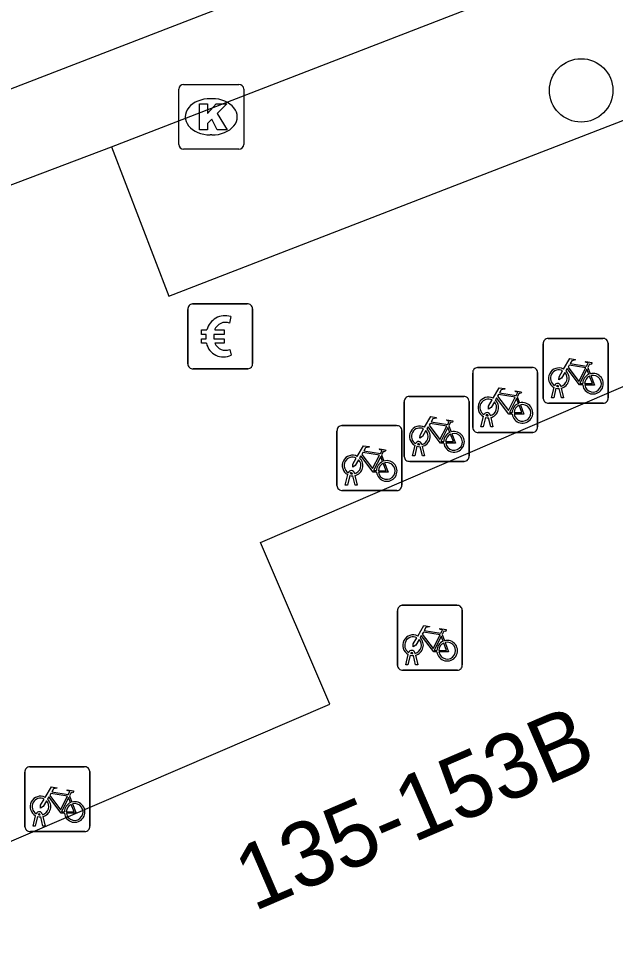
# Model space of a CAD drawing. Extents: x 159377 to 159983, y 382996 to 383595.
# Drawn here: x 159591.33 to 159600.52, y 383532.21 to 383546.59 of the extents above; entities that cross this region are included whole.
import ezdxf

# ---------------------------------------------------------------- set-up
doc = ezdxf.new("R2010")
doc.units = 0
for name, color, linetype in [('IMGEO_Betaalautomaat', 7, 'Continuous'), ('IMGEO_Boom', 7, 'Continuous'), ('IMGEO_Fietsenrek', 7, 'Continuous'), ('IMGEO_Kolk', 7, 'Continuous'), ('IMGEO_Pand', 7, 'Continuous'), ('IMGEO_Pand_nummerreeks', 7, 'Continuous'), ('IMGEO_Rijbaan_lokaal_gesloten', 7, 'Continuous'), ('IMGEO_Voetpad_open', 7, 'Continuous')]:
    doc.layers.add(name, color=color, linetype=linetype)

msp = doc.modelspace()

# ---------------------------------------------------------------- linework, layer by layer
at = {"layer": 'IMGEO_Betaalautomaat'}
for p, q in [((159593.934, 383541.268), (159593.934, 383542.109)), ((159593.934, 383542.109), (159593.934, 383541.268)), ((159594.009, 383542.192), (159594.85, 383542.192)), ((159594.85, 383542.192), (159594.009, 383542.192)), ((159594.933, 383542.118), (159594.933, 383541.277)), ((159594.933, 383541.277), (159594.933, 383542.118)), ((159594.596, 383541.997), (159594.579, 383541.897)), ((159594.217, 383541.656), (159594.217, 383541.724)), ((159594.338, 383541.724), (159594.338, 383541.656)), ((159594.583, 383541.491), (159594.605, 383541.404)), ((159594.859, 383541.193), (159594.018, 383541.193)), ((159594.018, 383541.193), (159594.859, 383541.193))]:
    msp.add_line(p, q, dxfattribs=at)
for points in [[(159594.217, 383541.724), (159594.148, 383541.724), (159594.148, 383541.793), (159594.227, 383541.793)], [(159594.349, 383541.793), (159594.496, 383541.793), (159594.496, 383541.724), (159594.338, 383541.724)], [(159594.222, 383541.587), (159594.148, 383541.587), (159594.148, 383541.656), (159594.217, 383541.656)], [(159594.338, 383541.656), (159594.496, 383541.656), (159594.496, 383541.587), (159594.352, 383541.587)]]:
    msp.add_lwpolyline(points, dxfattribs=at)
for centre, radius, start, end in [((159594.012, 383542.115), 0.0779, 92.4484, 184.2845), ((159594.012, 383542.115), 0.0779, 92.4484, 184.2845), ((159594.856, 383542.115), 0.0779, 2.4484, 94.2845), ((159594.856, 383542.115), 0.0779, 2.4484, 94.2845), ((159594.51, 383541.717), 0.293, 73.014, 165.0139), ((159594.516, 383541.73), 0.179, 69.3236, 159.5683), ((159594.483, 383541.642), 0.267, 191.8096, 297.0389), ((159594.516, 383541.657), 0.179, 202.7625, 291.8693), ((159594.012, 383541.271), 0.0779, 182.4484, 274.2845), ((159594.012, 383541.271), 0.0779, 182.4484, 274.2845), ((159594.856, 383541.271), 0.0779, 272.4484, 4.2845), ((159594.856, 383541.271), 0.0779, 272.4484, 4.2845)]:
    msp.add_arc(centre, radius, start, end, dxfattribs=at)
at = {"layer": 'IMGEO_Boom'}
msp.add_circle((159599.997, 383545.484), 0.489, dxfattribs=at)
at = {"layer": 'IMGEO_Fietsenrek'}
for p, q in [((159599.413, 383540.737), (159599.413, 383541.578)), ((159599.413, 383541.578), (159599.413, 383540.737)), ((159599.488, 383541.662), (159600.329, 383541.662)), ((159600.329, 383541.662), (159599.488, 383541.662)), ((159600.413, 383541.587), (159600.413, 383540.746)), ((159600.413, 383540.746), (159600.413, 383541.587)), ((159598.326, 383540.287), (159598.326, 383541.128)), ((159598.326, 383541.128), (159598.326, 383540.287)), ((159598.401, 383541.212), (159599.242, 383541.212)), ((159599.242, 383541.212), (159598.401, 383541.212)), ((159599.326, 383541.137), (159599.326, 383540.296)), ((159599.326, 383540.296), (159599.326, 383541.137)), ((159600.1, 383541.211), (159600.136, 383541.116)), ((159599.54, 383540.746), (159599.579, 383540.906)), ((159599.609, 383540.894), (159599.574, 383540.746)), ((159599.651, 383540.918), (159599.65, 383540.922)), ((159599.692, 383540.746), (159599.658, 383540.888)), ((159599.682, 383540.929), (159599.683, 383540.922)), ((159599.69, 383540.892), (159599.725, 383540.746)), ((159597.271, 383539.841), (159597.271, 383540.682)), ((159597.271, 383540.682), (159597.271, 383539.841)), ((159597.346, 383540.766), (159598.187, 383540.766)), ((159598.187, 383540.766), (159597.346, 383540.766)), ((159598.271, 383540.691), (159598.271, 383539.85)), ((159598.271, 383539.85), (159598.271, 383540.691)), ((159599.013, 383540.761), (159599.049, 383540.666)), ((159600.338, 383540.662), (159599.497, 383540.662)), ((159599.497, 383540.662), (159600.338, 383540.662)), ((159599.574, 383540.746), (159599.54, 383540.746)), ((159599.725, 383540.746), (159599.692, 383540.746)), ((159598.453, 383540.296), (159598.492, 383540.456)), ((159598.522, 383540.444), (159598.487, 383540.296)), ((159598.564, 383540.468), (159598.563, 383540.472)), ((159598.605, 383540.296), (159598.571, 383540.438)), ((159598.595, 383540.479), (159598.596, 383540.472)), ((159598.603, 383540.442), (159598.638, 383540.296)), ((159596.234, 383539.392), (159596.234, 383540.233)), ((159596.234, 383540.233), (159596.234, 383539.392)), ((159596.309, 383540.317), (159597.15, 383540.317)), ((159597.15, 383540.317), (159596.309, 383540.317)), ((159597.234, 383540.242), (159597.234, 383539.401)), ((159597.234, 383539.401), (159597.234, 383540.242)), ((159597.958, 383540.315), (159597.994, 383540.22)), ((159598.487, 383540.296), (159598.453, 383540.296)), ((159598.638, 383540.296), (159598.605, 383540.296)), ((159599.251, 383540.212), (159598.41, 383540.212)), ((159598.41, 383540.212), (159599.251, 383540.212)), ((159597.398, 383539.85), (159597.437, 383540.01)), ((159597.467, 383539.998), (159597.432, 383539.85)), ((159597.509, 383540.022), (159597.508, 383540.026)), ((159597.55, 383539.85), (159597.516, 383539.992)), ((159597.54, 383540.033), (159597.541, 383540.026)), ((159597.548, 383539.996), (159597.583, 383539.85)), ((159596.921, 383539.866), (159596.957, 383539.771)), ((159597.432, 383539.85), (159597.398, 383539.85)), ((159597.583, 383539.85), (159597.55, 383539.85)), ((159598.196, 383539.766), (159597.355, 383539.766)), ((159597.355, 383539.766), (159598.196, 383539.766)), ((159596.361, 383539.401), (159596.4, 383539.561)), ((159596.43, 383539.549), (159596.395, 383539.401)), ((159596.472, 383539.573), (159596.471, 383539.577)), ((159596.513, 383539.401), (159596.479, 383539.543)), ((159596.503, 383539.584), (159596.504, 383539.577)), ((159596.511, 383539.547), (159596.546, 383539.401)), ((159596.395, 383539.401), (159596.361, 383539.401)), ((159596.546, 383539.401), (159596.513, 383539.401)), ((159597.159, 383539.317), (159596.318, 383539.317)), ((159596.318, 383539.317), (159597.159, 383539.317)), ((159597.241, 383537.547), (159598.082, 383537.547)), ((159598.082, 383537.547), (159597.241, 383537.547)), ((159597.166, 383536.622), (159597.166, 383537.463)), ((159597.166, 383537.463), (159597.166, 383536.622)), ((159598.166, 383537.472), (159598.166, 383536.631)), ((159598.166, 383536.631), (159598.166, 383537.472)), ((159597.853, 383537.096), (159597.889, 383537.001)), ((159597.293, 383536.631), (159597.332, 383536.791)), ((159597.362, 383536.779), (159597.327, 383536.631)), ((159597.404, 383536.803), (159597.403, 383536.807)), ((159597.435, 383536.814), (159597.436, 383536.807)), ((159597.443, 383536.777), (159597.478, 383536.631)), ((159597.445, 383536.631), (159597.411, 383536.773)), ((159598.091, 383536.547), (159597.25, 383536.547)), ((159597.25, 383536.547), (159598.091, 383536.547)), ((159597.327, 383536.631), (159597.293, 383536.631)), ((159597.478, 383536.631), (159597.445, 383536.631)), ((159591.499, 383535.06), (159592.34, 383535.06)), ((159592.34, 383535.06), (159591.499, 383535.06)), ((159591.424, 383534.135), (159591.424, 383534.976)), ((159591.424, 383534.976), (159591.424, 383534.135)), ((159592.424, 383534.985), (159592.424, 383534.144)), ((159592.424, 383534.144), (159592.424, 383534.985)), ((159592.111, 383534.609), (159592.147, 383534.514)), ((159591.551, 383534.144), (159591.59, 383534.304)), ((159591.62, 383534.292), (159591.585, 383534.144)), ((159591.662, 383534.316), (159591.661, 383534.32)), ((159591.703, 383534.144), (159591.669, 383534.286)), ((159591.693, 383534.327), (159591.694, 383534.32)), ((159591.701, 383534.29), (159591.736, 383534.144)), ((159592.349, 383534.06), (159591.508, 383534.06)), ((159591.508, 383534.06), (159592.349, 383534.06)), ((159591.585, 383534.144), (159591.551, 383534.144)), ((159591.736, 383534.144), (159591.703, 383534.144))]:
    msp.add_line(p, q, dxfattribs=at)
for points in [[(159599.726, 383541.188), (159599.821, 383541.352), (159599.907, 383541.338), (159599.909, 383541.329), (159599.853, 383541.318), (159599.826, 383541.273), (159600.082, 383541.232)], [(159600.069, 383541.207), (159599.812, 383541.248), (159599.795, 383541.219), (159599.962, 383540.999), (159600.069, 383541.207)], [(159600.082, 383541.232), (159600.107, 383541.281), (159600.101, 383541.285), (159600.078, 383541.289), (159600.066, 383541.296), (159600.065, 383541.299), (159600.067, 383541.304), (159600.162, 383541.289), (159600.164, 383541.279), (159600.154, 383541.266), (159600.142, 383541.26), (159600.128, 383541.266), (159600.1, 383541.211)], [(159599.747, 383541.136), (159599.695, 383541.046), (159599.655, 383541.021), (159599.656, 383541.068), (159599.711, 383541.162)], [(159600.022, 383540.944), (159599.972, 383540.944), (159599.781, 383541.195), (159599.762, 383541.163)], [(159600.117, 383541.109), (159600.087, 383541.186), (159599.978, 383540.968), (159600.021, 383540.968)], [(159600.051, 383540.968), (159600.171, 383540.967), (159600.127, 383541.081)], [(159600.147, 383541.088), (159600.202, 383540.943), (159600.052, 383540.943)], [(159598.639, 383540.738), (159598.734, 383540.902), (159598.82, 383540.888), (159598.822, 383540.879), (159598.766, 383540.868), (159598.739, 383540.823), (159598.995, 383540.782)], [(159598.995, 383540.782), (159599.02, 383540.831), (159599.014, 383540.835), (159598.991, 383540.839), (159598.979, 383540.846), (159598.978, 383540.849), (159598.98, 383540.854), (159599.075, 383540.839), (159599.077, 383540.829), (159599.067, 383540.816), (159599.055, 383540.81), (159599.041, 383540.816), (159599.013, 383540.761)], [(159598.66, 383540.686), (159598.608, 383540.596), (159598.568, 383540.571), (159598.569, 383540.618), (159598.624, 383540.712)], [(159598.935, 383540.494), (159598.885, 383540.494), (159598.694, 383540.745), (159598.675, 383540.713)], [(159598.982, 383540.757), (159598.725, 383540.798), (159598.708, 383540.769), (159598.875, 383540.549), (159598.982, 383540.757)], [(159599.03, 383540.659), (159599, 383540.736), (159598.891, 383540.518), (159598.934, 383540.518)], [(159598.964, 383540.518), (159599.084, 383540.517), (159599.04, 383540.631)], [(159599.06, 383540.638), (159599.115, 383540.493), (159598.965, 383540.493)], [(159597.584, 383540.292), (159597.679, 383540.456), (159597.765, 383540.442), (159597.767, 383540.433), (159597.711, 383540.422), (159597.684, 383540.377), (159597.94, 383540.336)], [(159597.94, 383540.336), (159597.965, 383540.385), (159597.959, 383540.389), (159597.936, 383540.393), (159597.924, 383540.4), (159597.923, 383540.403), (159597.925, 383540.408), (159598.02, 383540.393), (159598.022, 383540.383), (159598.012, 383540.37), (159598, 383540.364), (159597.986, 383540.37), (159597.958, 383540.315)], [(159597.605, 383540.24), (159597.553, 383540.15), (159597.513, 383540.125), (159597.514, 383540.172), (159597.569, 383540.266)], [(159597.88, 383540.048), (159597.83, 383540.048), (159597.639, 383540.299), (159597.62, 383540.267)], [(159597.927, 383540.311), (159597.67, 383540.352), (159597.653, 383540.323), (159597.82, 383540.103), (159597.927, 383540.311)], [(159597.975, 383540.213), (159597.945, 383540.29), (159597.836, 383540.072), (159597.879, 383540.072)], [(159597.909, 383540.072), (159598.029, 383540.071), (159597.985, 383540.185)], [(159598.005, 383540.192), (159598.06, 383540.047), (159597.91, 383540.047)], [(159596.547, 383539.843), (159596.642, 383540.007), (159596.728, 383539.993), (159596.73, 383539.984), (159596.674, 383539.973), (159596.647, 383539.928), (159596.903, 383539.887)], [(159596.903, 383539.887), (159596.928, 383539.936), (159596.922, 383539.94), (159596.899, 383539.944), (159596.887, 383539.951), (159596.886, 383539.954), (159596.888, 383539.959), (159596.983, 383539.944), (159596.985, 383539.934), (159596.975, 383539.921), (159596.963, 383539.915), (159596.949, 383539.921), (159596.921, 383539.866)], [(159596.568, 383539.791), (159596.516, 383539.701), (159596.476, 383539.676), (159596.477, 383539.723), (159596.532, 383539.817)], [(159596.843, 383539.599), (159596.793, 383539.599), (159596.602, 383539.85), (159596.583, 383539.818)], [(159596.89, 383539.862), (159596.633, 383539.903), (159596.616, 383539.874), (159596.783, 383539.654), (159596.89, 383539.862)], [(159596.938, 383539.764), (159596.908, 383539.841), (159596.799, 383539.623), (159596.842, 383539.623)], [(159596.872, 383539.623), (159596.992, 383539.622), (159596.948, 383539.736)], [(159596.968, 383539.743), (159597.023, 383539.598), (159596.873, 383539.598)], [(159597.479, 383537.073), (159597.574, 383537.237), (159597.66, 383537.223), (159597.662, 383537.214), (159597.606, 383537.203), (159597.579, 383537.158), (159597.835, 383537.117)], [(159597.775, 383536.829), (159597.725, 383536.829), (159597.534, 383537.08), (159597.515, 383537.048)], [(159597.822, 383537.092), (159597.565, 383537.133), (159597.548, 383537.104), (159597.715, 383536.884), (159597.822, 383537.092)], [(159597.87, 383536.994), (159597.84, 383537.071), (159597.731, 383536.853), (159597.774, 383536.853)], [(159597.835, 383537.117), (159597.86, 383537.166), (159597.854, 383537.17), (159597.831, 383537.174), (159597.819, 383537.181), (159597.818, 383537.184), (159597.82, 383537.189), (159597.915, 383537.174), (159597.917, 383537.164), (159597.907, 383537.151), (159597.895, 383537.145), (159597.881, 383537.151), (159597.853, 383537.096)], [(159597.5, 383537.021), (159597.448, 383536.931), (159597.408, 383536.906), (159597.409, 383536.953), (159597.464, 383537.047)], [(159597.804, 383536.853), (159597.924, 383536.852), (159597.88, 383536.966)], [(159597.9, 383536.973), (159597.955, 383536.828), (159597.805, 383536.828)], [(159591.737, 383534.586), (159591.832, 383534.75), (159591.918, 383534.736), (159591.92, 383534.727), (159591.864, 383534.716), (159591.837, 383534.671), (159592.093, 383534.63)], [(159592.08, 383534.605), (159591.823, 383534.646), (159591.806, 383534.617), (159591.973, 383534.397), (159592.08, 383534.605)], [(159592.093, 383534.63), (159592.118, 383534.679), (159592.112, 383534.683), (159592.089, 383534.687), (159592.077, 383534.694), (159592.076, 383534.697), (159592.078, 383534.702), (159592.173, 383534.687), (159592.175, 383534.677), (159592.165, 383534.664), (159592.153, 383534.658), (159592.139, 383534.664), (159592.111, 383534.609)], [(159591.758, 383534.534), (159591.706, 383534.444), (159591.666, 383534.419), (159591.667, 383534.466), (159591.722, 383534.56)], [(159592.033, 383534.342), (159591.983, 383534.342), (159591.792, 383534.593), (159591.773, 383534.561)], [(159592.128, 383534.507), (159592.098, 383534.584), (159591.989, 383534.366), (159592.032, 383534.366)], [(159592.062, 383534.366), (159592.182, 383534.365), (159592.138, 383534.479)], [(159592.158, 383534.486), (159592.213, 383534.341), (159592.063, 383534.341)]]:
    msp.add_lwpolyline(points, dxfattribs=at)
for centre, radius, start, end in [((159599.491, 383541.584), 0.0779, 92.4484, 184.2845), ((159599.491, 383541.584), 0.0779, 92.4484, 184.2845), ((159600.335, 383541.584), 0.0779, 2.4484, 94.2845), ((159600.335, 383541.584), 0.0779, 2.4484, 94.2845), ((159598.404, 383541.134), 0.0779, 92.4484, 184.2845), ((159598.404, 383541.134), 0.0779, 92.4484, 184.2845), ((159599.248, 383541.134), 0.0779, 2.4484, 94.2845), ((159599.248, 383541.134), 0.0779, 2.4484, 94.2845), ((159599.653, 383541.047), 0.159, 62.6766, 242.1369), ((159599.653, 383541.047), 0.129, 63.3192, 238.903), ((159599.653, 383541.047), 0.129, 283.6043, 43.4302), ((159599.653, 383541.047), 0.159, 283.5766, 46.6042), ((159600.18, 383540.963), 0.159, 113.3408, 178.3217), ((159600.18, 383540.963), 0.159, 187.0065, 105.7708), ((159600.18, 383540.963), 0.129, 188.6715, 104.5883), ((159599.633, 383540.918), 0.0499, 12.8025, 158.6934), ((159600.18, 383540.963), 0.129, 113.923, 177.9556), ((159599.653, 383541.047), 0.159, 253.9967, 271.7867), ((159599.633, 383540.918), 0.0174, 12.8025, 163.4502), ((159599.653, 383541.047), 0.129, 253.415, 269.0204), ((159597.349, 383540.688), 0.0779, 92.4484, 184.2845), ((159597.349, 383540.688), 0.0779, 92.4484, 184.2845), ((159598.193, 383540.688), 0.0779, 2.4484, 94.2845), ((159598.193, 383540.688), 0.0779, 2.4484, 94.2845), ((159598.566, 383540.597), 0.159, 62.6766, 242.1369), ((159598.566, 383540.597), 0.129, 63.3192, 238.903), ((159598.566, 383540.597), 0.129, 283.6043, 43.4302), ((159598.566, 383540.597), 0.159, 283.5766, 46.6042), ((159599.093, 383540.513), 0.159, 113.3408, 178.3217), ((159599.093, 383540.513), 0.159, 187.0065, 105.7708), ((159599.491, 383540.74), 0.0779, 182.4484, 274.2845), ((159599.491, 383540.74), 0.0779, 182.4484, 274.2845), ((159600.335, 383540.74), 0.0779, 272.4484, 4.2845), ((159600.335, 383540.74), 0.0779, 272.4484, 4.2845), ((159598.546, 383540.468), 0.0499, 12.8025, 158.6934), ((159599.093, 383540.513), 0.129, 113.923, 177.9556), ((159599.093, 383540.513), 0.129, 188.6715, 104.5883), ((159598.566, 383540.597), 0.159, 253.9967, 271.7867), ((159598.546, 383540.468), 0.0174, 12.8025, 163.4502), ((159598.566, 383540.597), 0.129, 253.415, 269.0204), ((159596.312, 383540.239), 0.0779, 92.4484, 184.2845), ((159596.312, 383540.239), 0.0779, 92.4484, 184.2845), ((159597.156, 383540.239), 0.0779, 2.4484, 94.2845), ((159597.156, 383540.239), 0.0779, 2.4484, 94.2845), ((159597.511, 383540.151), 0.159, 62.6766, 242.1369), ((159597.511, 383540.151), 0.129, 63.3192, 238.903), ((159597.511, 383540.151), 0.129, 283.6043, 43.4302), ((159597.511, 383540.151), 0.159, 283.5766, 46.6042), ((159598.404, 383540.29), 0.0779, 182.4484, 274.2845), ((159598.404, 383540.29), 0.0779, 182.4484, 274.2845), ((159599.248, 383540.29), 0.0779, 272.4484, 4.2845), ((159599.248, 383540.29), 0.0779, 272.4484, 4.2845), ((159598.038, 383540.067), 0.159, 113.3408, 178.3217), ((159598.038, 383540.067), 0.159, 187.0065, 105.7708), ((159598.038, 383540.067), 0.129, 113.923, 177.9556), ((159598.038, 383540.067), 0.129, 188.6715, 104.5883), ((159597.491, 383540.022), 0.0499, 12.8025, 158.6934), ((159597.511, 383540.151), 0.159, 253.9967, 271.7867), ((159597.491, 383540.022), 0.0174, 12.8025, 163.4502), ((159597.511, 383540.151), 0.129, 253.415, 269.0204), ((159596.474, 383539.702), 0.159, 62.6766, 242.1369), ((159596.474, 383539.702), 0.129, 63.3192, 238.903), ((159596.474, 383539.702), 0.159, 283.5766, 46.6042), ((159597.349, 383539.844), 0.0779, 182.4484, 274.2845), ((159597.349, 383539.844), 0.0779, 182.4484, 274.2845), ((159598.193, 383539.844), 0.0779, 272.4484, 4.2845), ((159598.193, 383539.844), 0.0779, 272.4484, 4.2845), ((159596.474, 383539.702), 0.129, 283.6043, 43.4302), ((159597.001, 383539.618), 0.159, 113.3408, 178.3217), ((159597.001, 383539.618), 0.159, 187.0065, 105.7708), ((159597.001, 383539.618), 0.129, 113.923, 177.9556), ((159597.001, 383539.618), 0.129, 188.6715, 104.5883), ((159596.454, 383539.573), 0.0499, 12.8025, 158.6934), ((159596.474, 383539.702), 0.159, 253.9967, 271.7867), ((159596.454, 383539.573), 0.0174, 12.8025, 163.4502), ((159596.474, 383539.702), 0.129, 253.415, 269.0204), ((159596.312, 383539.395), 0.0779, 182.4484, 274.2845), ((159596.312, 383539.395), 0.0779, 182.4484, 274.2845), ((159597.156, 383539.395), 0.0779, 272.4484, 4.2845), ((159597.156, 383539.395), 0.0779, 272.4484, 4.2845), ((159597.244, 383537.469), 0.0779, 92.4484, 184.2845), ((159597.244, 383537.469), 0.0779, 92.4484, 184.2845), ((159598.088, 383537.469), 0.0779, 2.4484, 94.2845), ((159598.088, 383537.469), 0.0779, 2.4484, 94.2845), ((159597.406, 383536.932), 0.159, 62.6766, 242.1369), ((159597.406, 383536.932), 0.129, 63.3192, 238.903), ((159597.406, 383536.932), 0.129, 283.6043, 43.4302), ((159597.406, 383536.932), 0.159, 283.5766, 46.6042), ((159597.933, 383536.848), 0.159, 113.3408, 178.3217), ((159597.933, 383536.848), 0.159, 187.0065, 105.7708), ((159597.933, 383536.848), 0.129, 113.923, 177.9556), ((159597.933, 383536.848), 0.129, 188.6715, 104.5883), ((159597.386, 383536.803), 0.0499, 12.8025, 158.6934), ((159597.406, 383536.932), 0.159, 253.9967, 271.7867), ((159597.386, 383536.803), 0.0174, 12.8025, 163.4502), ((159597.406, 383536.932), 0.129, 253.415, 269.0204), ((159597.244, 383536.625), 0.0779, 182.4484, 274.2845), ((159597.244, 383536.625), 0.0779, 182.4484, 274.2845), ((159598.088, 383536.625), 0.0779, 272.4484, 4.2845), ((159598.088, 383536.625), 0.0779, 272.4484, 4.2845), ((159591.502, 383534.982), 0.0779, 92.4484, 184.2845), ((159591.502, 383534.982), 0.0779, 92.4484, 184.2845), ((159592.346, 383534.982), 0.0779, 2.4484, 94.2845), ((159592.346, 383534.982), 0.0779, 2.4484, 94.2845), ((159591.664, 383534.445), 0.159, 62.6766, 242.1369), ((159591.664, 383534.445), 0.129, 63.3192, 238.903), ((159591.664, 383534.445), 0.129, 283.6043, 43.4302), ((159591.664, 383534.445), 0.159, 283.5766, 46.6042), ((159592.191, 383534.361), 0.159, 113.3408, 178.3217), ((159592.191, 383534.361), 0.159, 187.0065, 105.7708), ((159592.191, 383534.361), 0.129, 113.923, 177.9556), ((159592.191, 383534.361), 0.129, 188.6715, 104.5883), ((159591.644, 383534.316), 0.0499, 12.8025, 158.6934), ((159591.644, 383534.316), 0.0174, 12.8025, 163.4502), ((159591.664, 383534.445), 0.159, 253.9967, 271.7867), ((159591.664, 383534.445), 0.129, 253.415, 269.0204), ((159591.502, 383534.138), 0.0779, 182.4484, 274.2845), ((159591.502, 383534.138), 0.0779, 182.4484, 274.2845), ((159592.346, 383534.138), 0.0779, 272.4484, 4.2845), ((159592.346, 383534.138), 0.0779, 272.4484, 4.2845)]:
    msp.add_arc(centre, radius, start, end, dxfattribs=at)
at = {"layer": 'IMGEO_Kolk'}
for p, q in [((159593.871, 383545.577), (159594.723, 383545.577)), ((159593.796, 383544.651), (159593.796, 383545.503)), ((159594.797, 383545.503), (159594.797, 383544.651)), ((159594.284, 383545.357), (159594.309, 383545.357)), ((159594.307, 383544.797), (159594.282, 383544.797)), ((159594.723, 383544.577), (159593.871, 383544.577))]:
    msp.add_line(p, q, dxfattribs=at)
for points in [[(159593.871, 383545.577), (159594.723, 383545.577)], [(159593.796, 383544.651), (159593.796, 383545.503)], [(159594.797, 383545.503), (159594.797, 383544.651)], [(159594.117, 383545.277), (159594.24, 383545.277), (159594.24, 383545.126), (159594.37, 383545.277), (159594.534, 383545.277), (159594.388, 383545.126), (159594.541, 383544.877), (159594.389, 383544.877), (159594.304, 383545.041), (159594.24, 383544.974), (159594.24, 383544.877), (159594.117, 383544.877), (159594.117, 383545.277)], [(159594.723, 383544.577), (159593.871, 383544.577)]]:
    msp.add_lwpolyline(points, dxfattribs=at)
for centre, start, end in [((159593.873, 383545.501), 91.552, 178.448), ((159593.873, 383545.501), 91.552, 178.448), ((159594.721, 383545.501), 1.552, 88.448), ((159594.721, 383545.501), 1.552, 88.448), ((159593.873, 383544.653), 181.552, 268.448), ((159593.873, 383544.653), 181.552, 268.448), ((159594.721, 383544.653), 271.552, 358.448), ((159594.721, 383544.653), 271.552, 358.448)]:
    msp.add_arc(centre, 0.0765, start, end, dxfattribs=at)
for centre, major_axis, ratio, start_param, end_param in [((159594.283, 383545.077), (-0.387, 0.002), 0.722429, 4.712389, 7.853982), ((159594.308, 383545.077), (-0.39, 0.002), 0.717154, 1.570796, 4.712389)]:
    msp.add_ellipse(centre, major_axis=major_axis, ratio=ratio, start_param=start_param, end_param=end_param, dxfattribs=at)
at = {"layer": 'IMGEO_Pand'}
msp.add_lwpolyline([(159554.458, 383512.889), (159557.863, 383515.315), (159557.41, 383516.394), (159562.464, 383518.516), (159561.396, 383521.059), (159576.35, 383527.523), (159596.126, 383536.025), (159595.056, 383538.515), (159614.892, 383547.056), (159630.263, 383553.702)], dxfattribs=at)
at = {"layer": 'IMGEO_Rijbaan_lokaal_gesloten'}
for points in [[(159575.588, 383539.471), (159588.74, 383544.556), (159601.118, 383549.342), (159621.266, 383557.067), (159621.788, 383555.845)], [(159592.76, 383544.616), (159621.788, 383555.845)], [(159587.149, 383542.49), (159592.76, 383544.616)]]:
    msp.add_lwpolyline(points, dxfattribs=at)
at = {"layer": 'IMGEO_Voetpad_open'}
msp.add_lwpolyline([(159592.76, 383544.616), (159593.644, 383542.314), (159622.719, 383553.571), (159621.788, 383555.845)], dxfattribs=at)

# ---------------------------------------------------------------- texts
at = {"layer": 'IMGEO_Pand_nummerreeks'}
msp.add_text('135-153B', height=1, rotation=23.3366, dxfattribs=at).set_placement((159594.952, 383532.822))

doc.saveas('drawing.dxf')
